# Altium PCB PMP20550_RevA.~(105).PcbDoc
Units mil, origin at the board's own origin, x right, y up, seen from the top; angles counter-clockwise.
Board outline 1966.66 x 1968.77 mil, 4 copper layers (Top Layer, POWER, GNDS, Bottom Layer), stack 79.834 mil thick; 55 components, 23 nets, 128 pads, 85 vias.
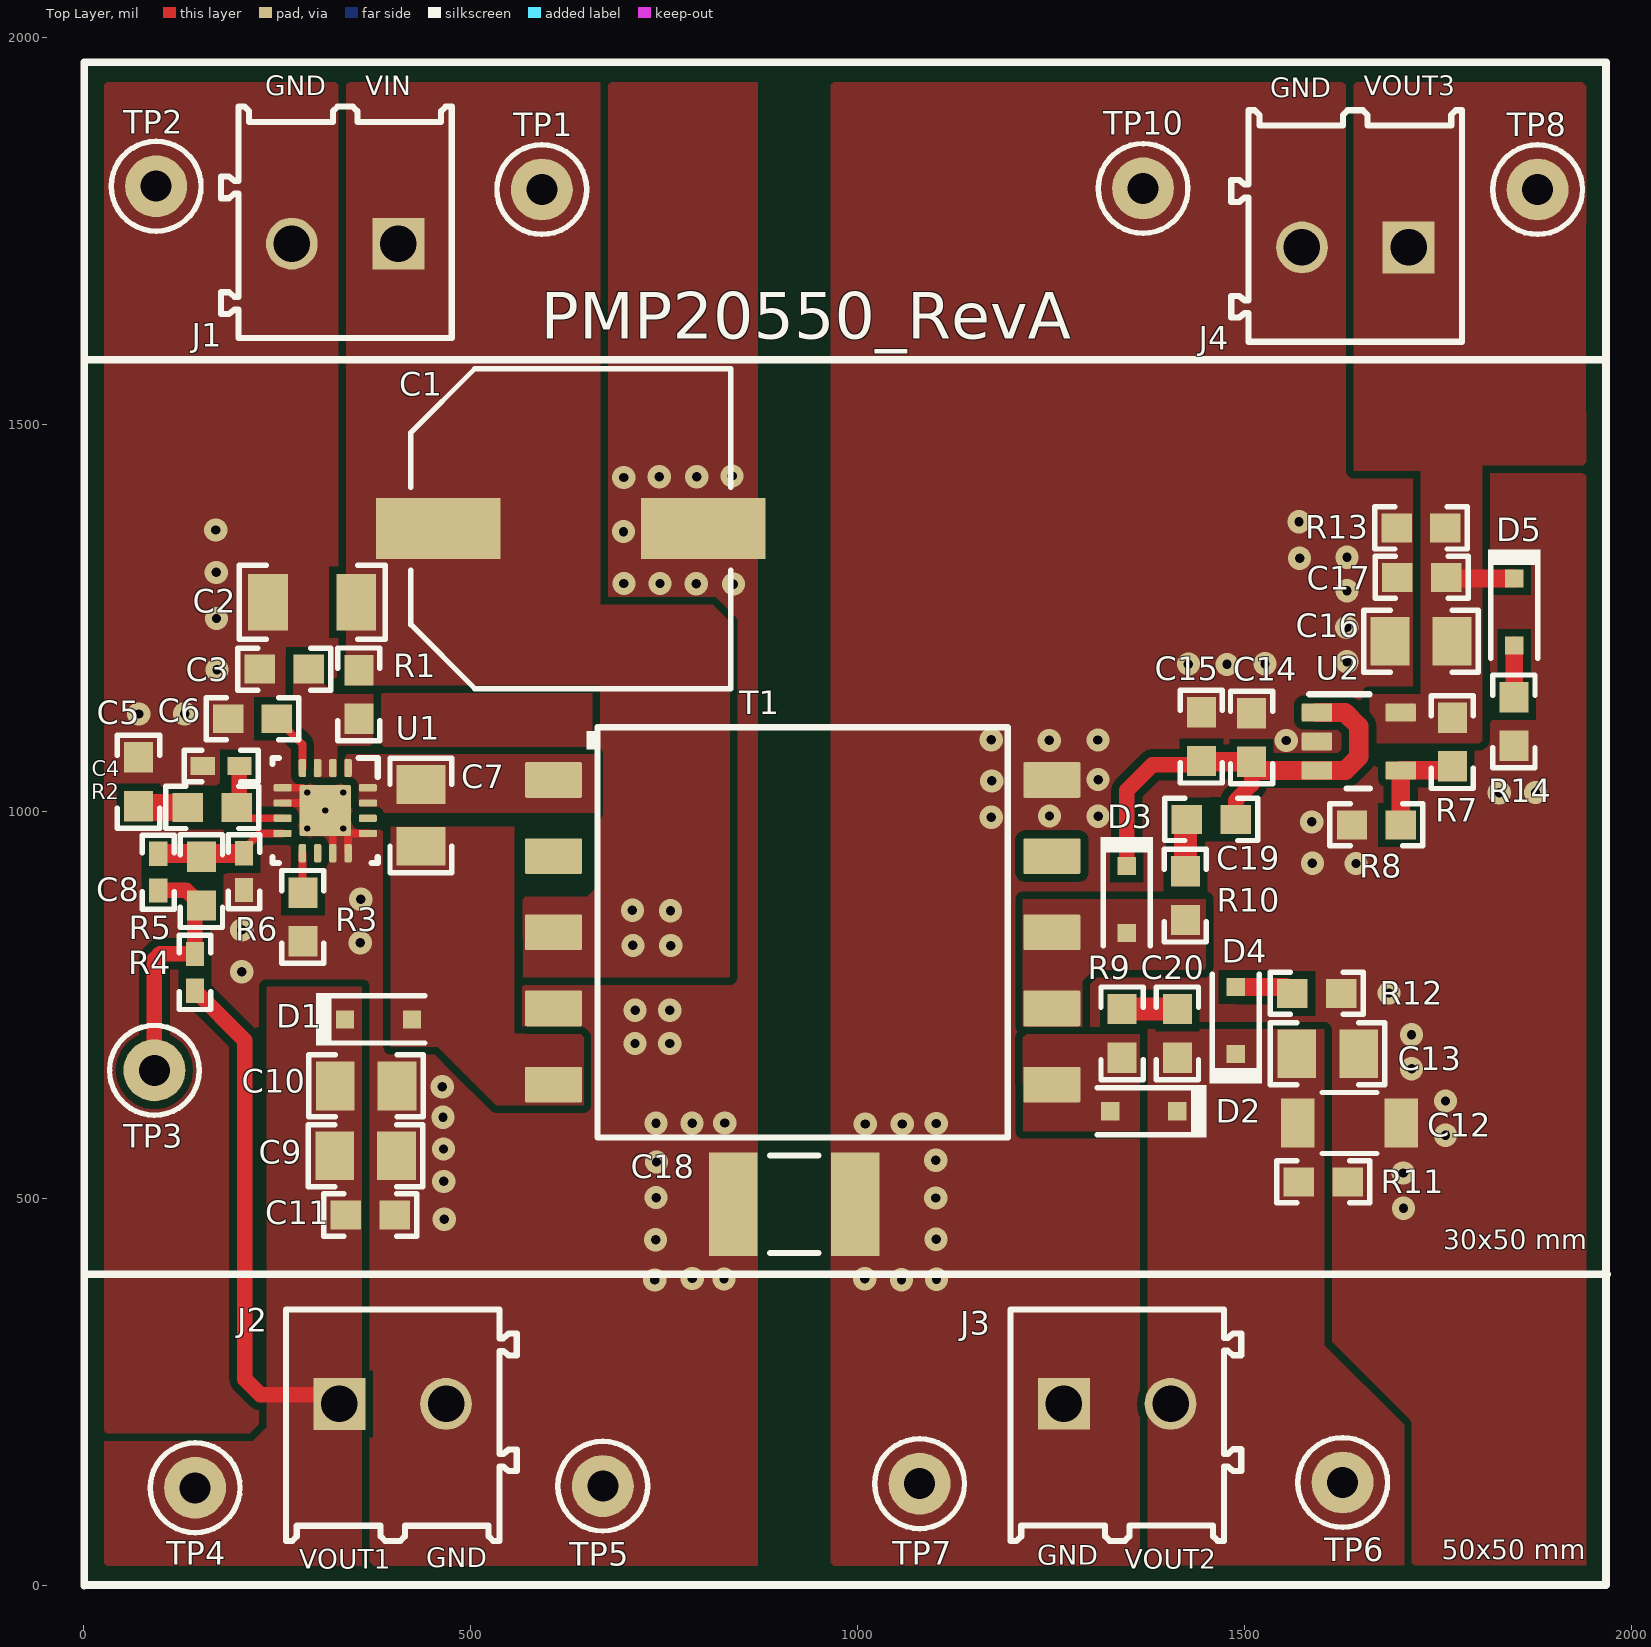
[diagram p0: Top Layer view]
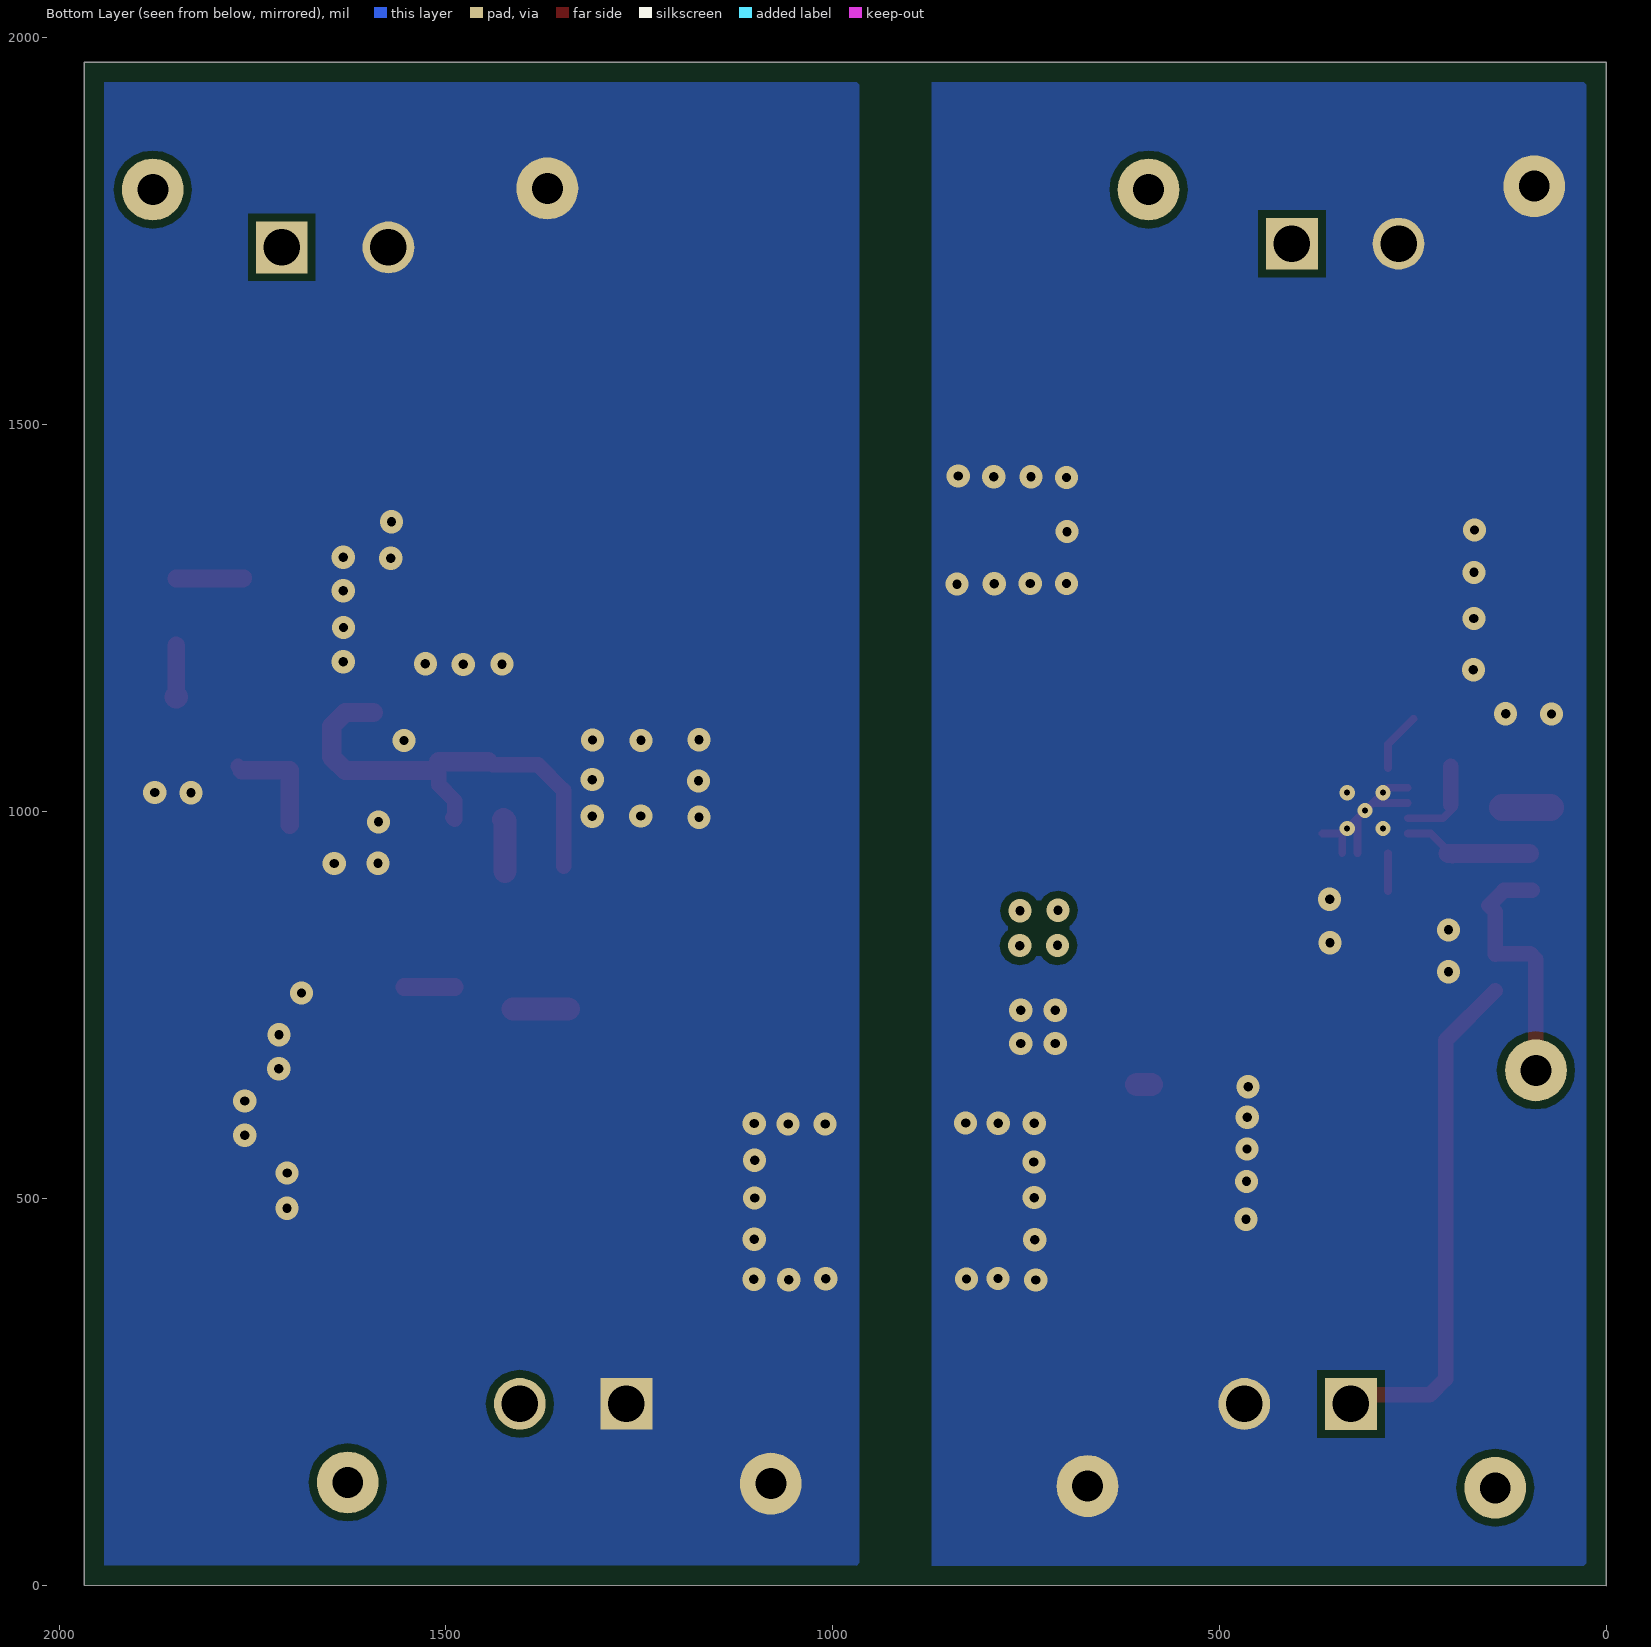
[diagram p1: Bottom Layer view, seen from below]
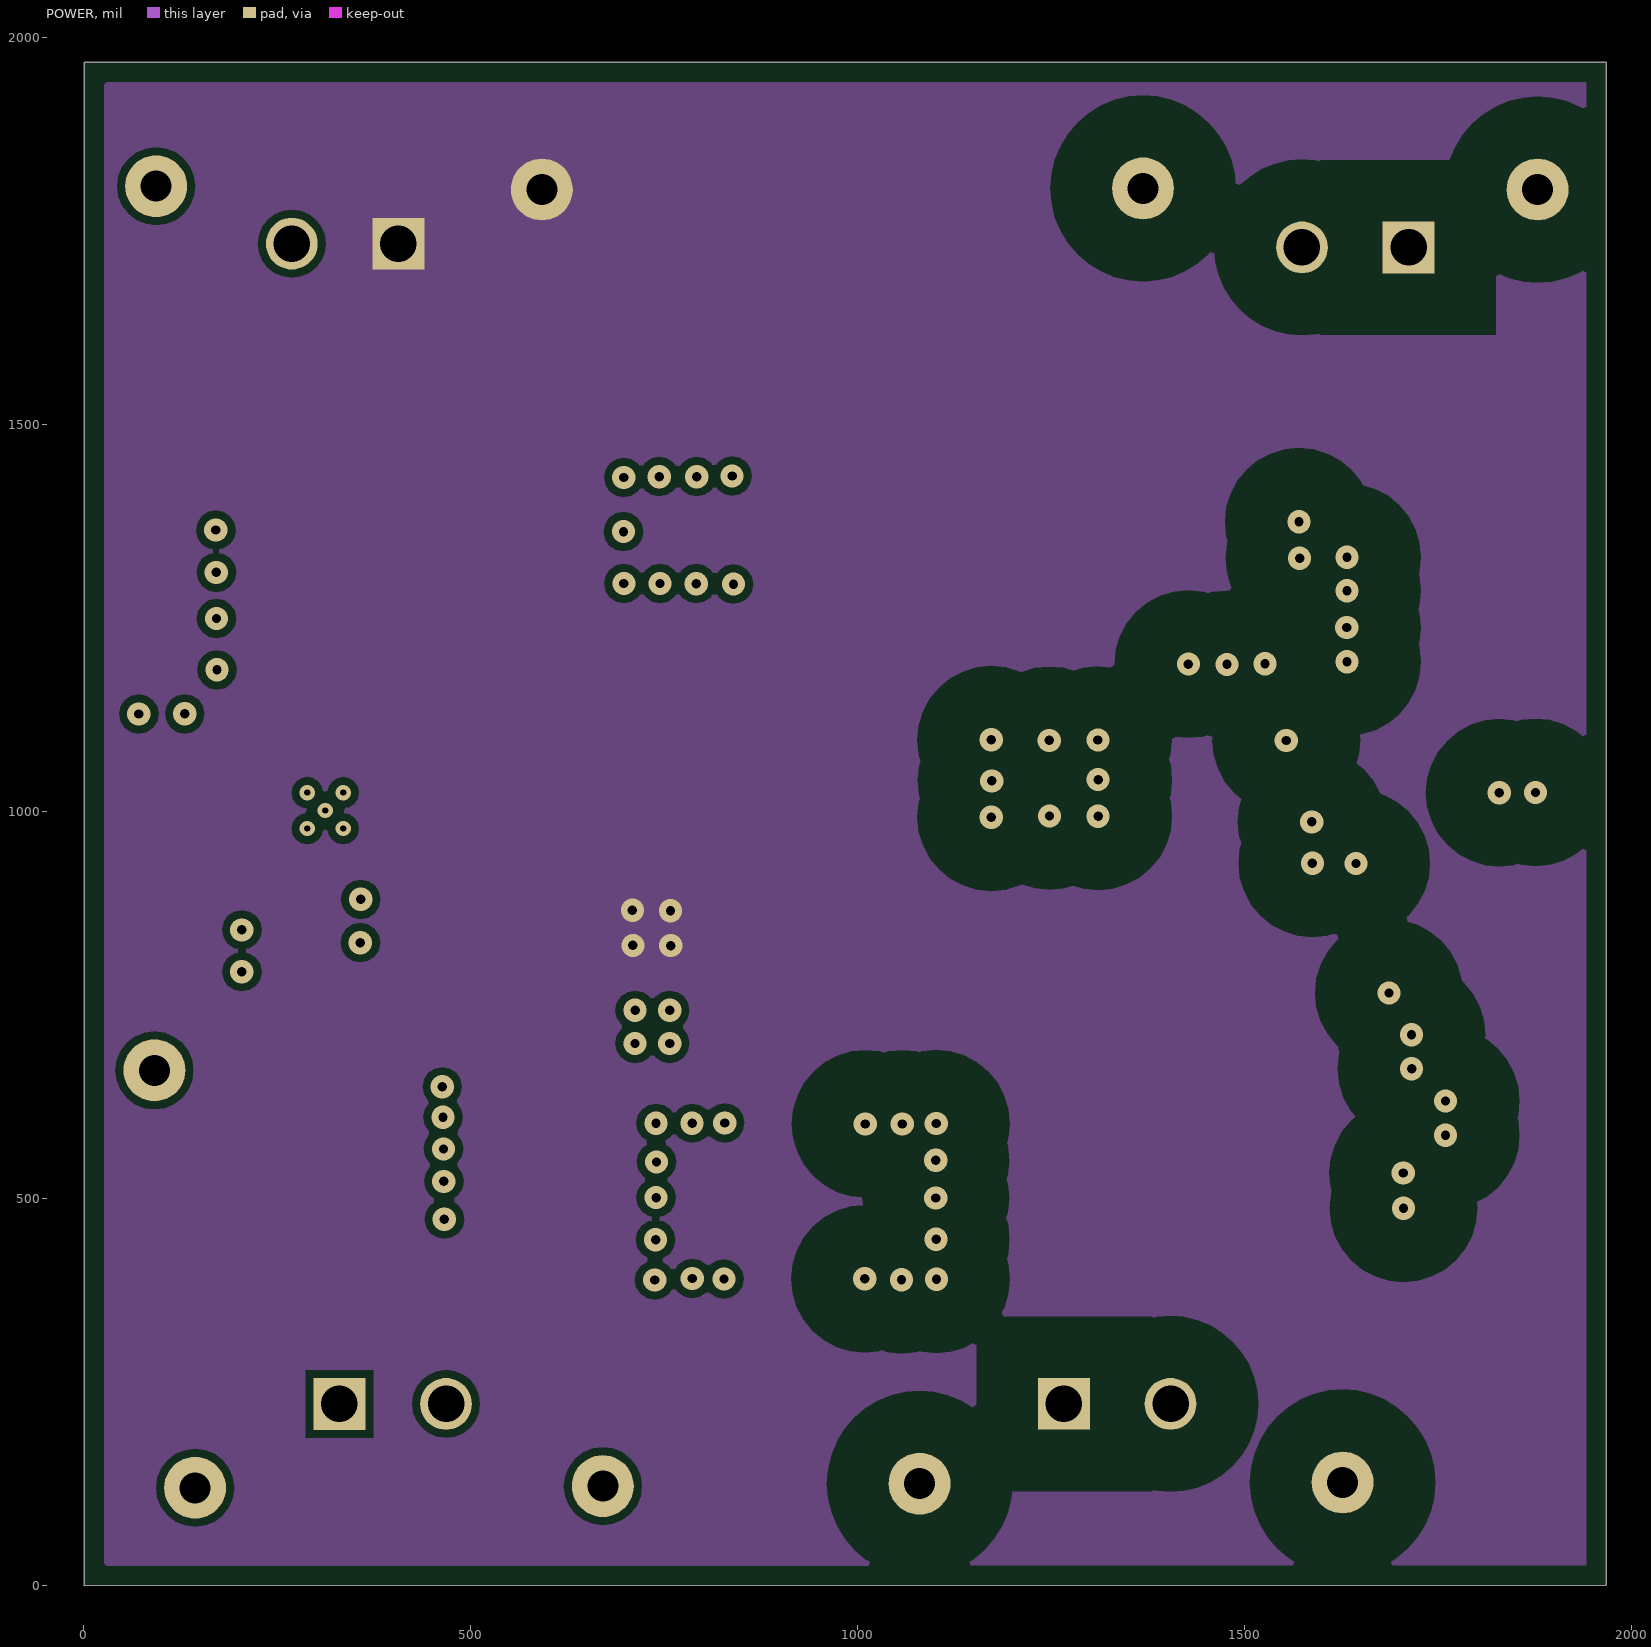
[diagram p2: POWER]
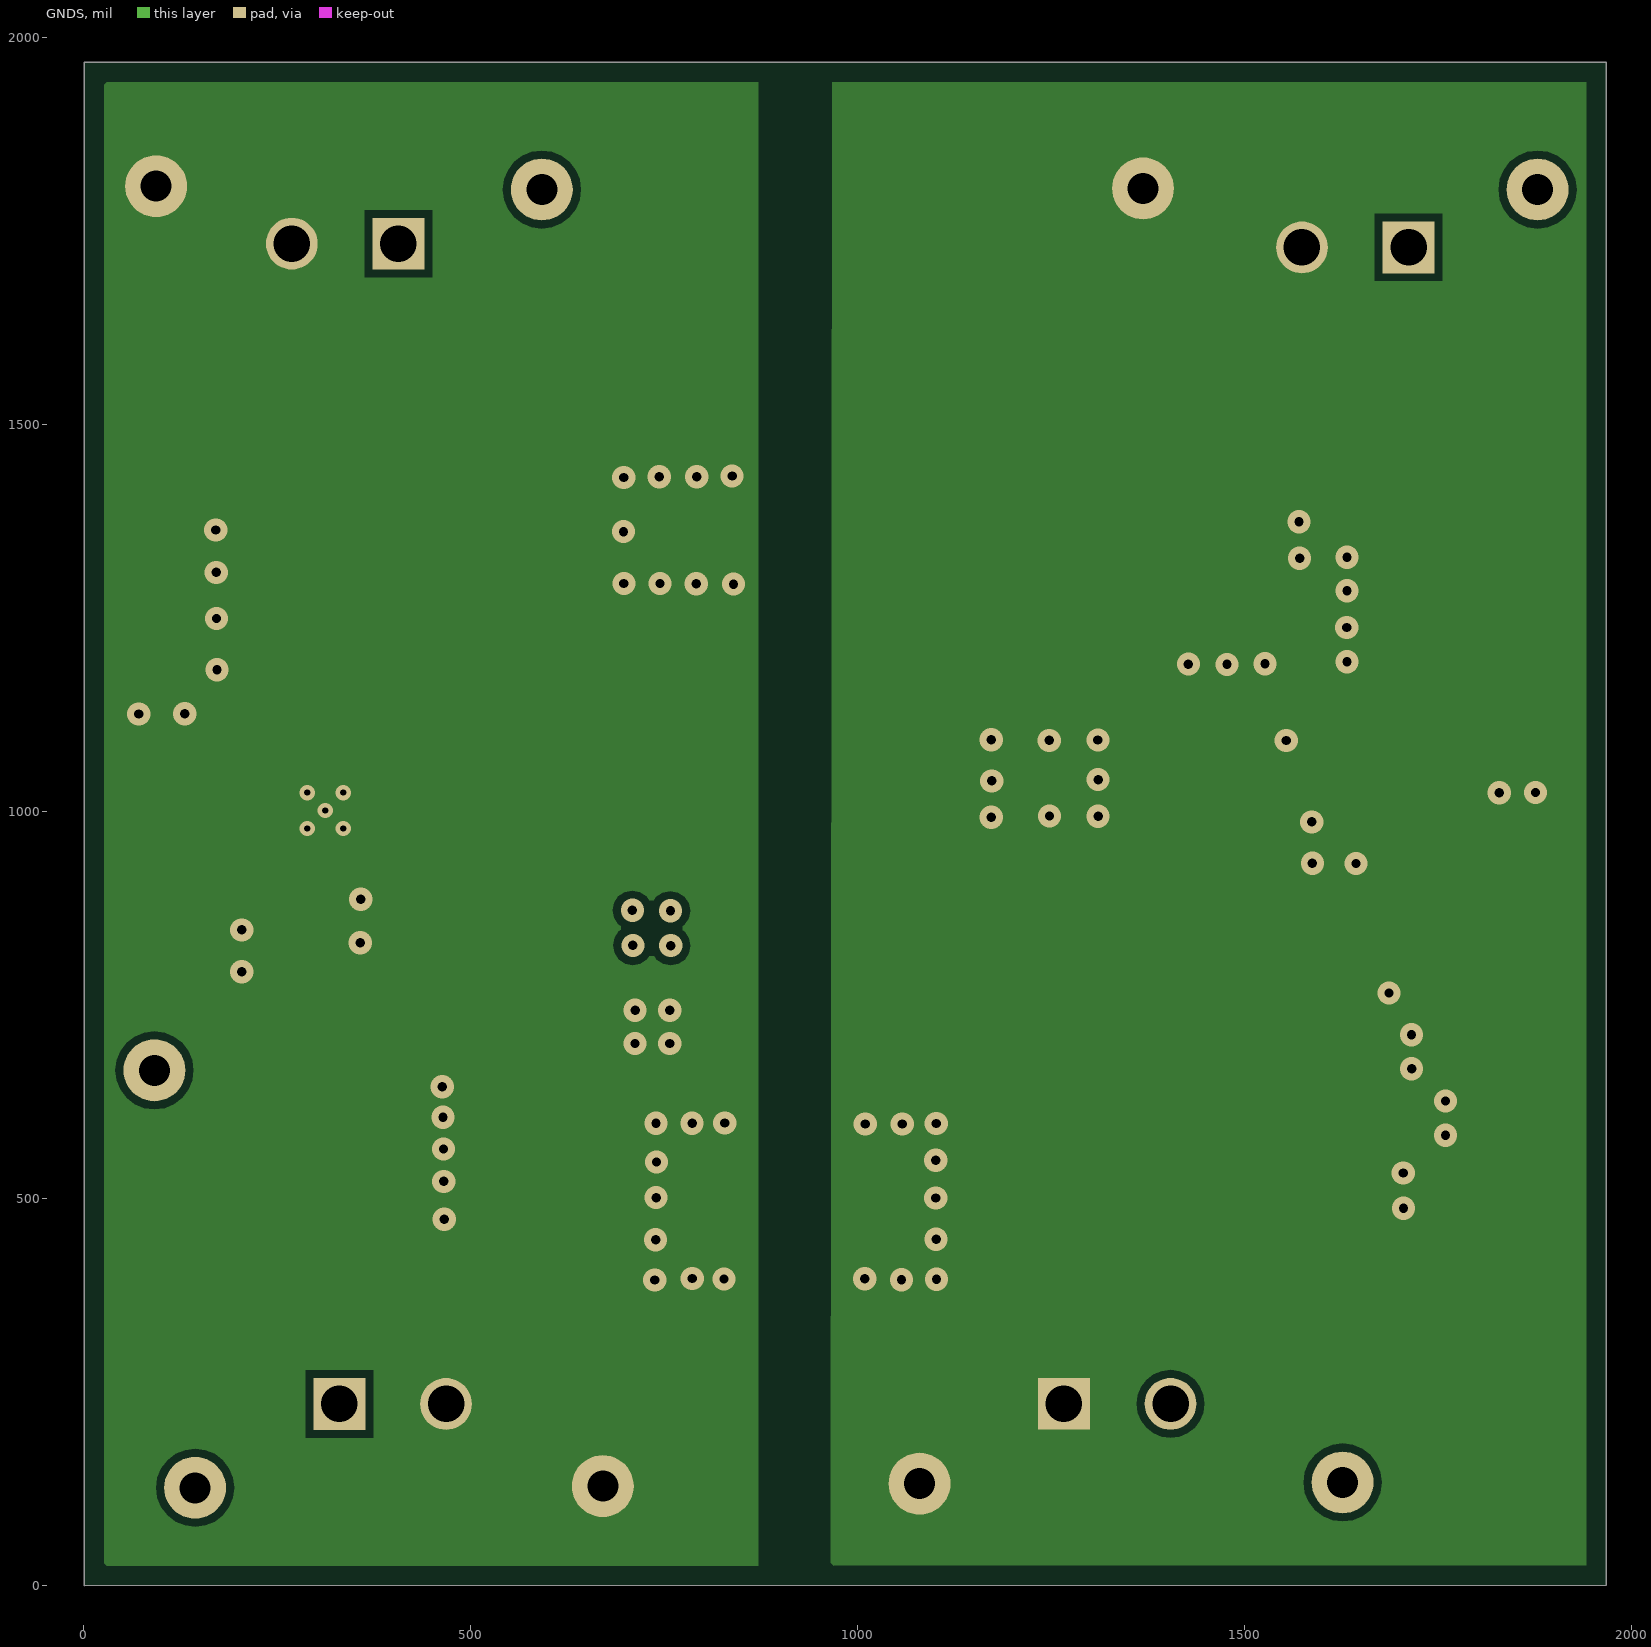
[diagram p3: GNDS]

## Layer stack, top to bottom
Top Solder: solder mask 0.4, Solder Resist, Dk 3.5
Top Layer: signal copper 1.4
Dielectric1: core 59.2, FR-4, Dk 4.8
POWER: signal copper 1.417
Dielectric 3: prepreg 5, Dk 4.2
GNDS: signal copper 1.417
Dielectric 2: core 10, Dk 4.2
Bottom Layer: signal copper 1.4
Bottom Solder: solder mask 0.4, Solder Resist, Dk 3.5

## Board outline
0.76,-0.43 0.76,1968.34 0.81,1968.29 1967.33,1968.29 1967.42,1968.2 1967.42,0.32 1967.36,0.38

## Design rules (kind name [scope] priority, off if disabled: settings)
AcuteAngle [All] p1: minimum=4.50000000000000E+0001 checktracksonly=FALSE
AssemblyTestPointUsage [All] p1: valid=2
BoardOutlineClearance BoardOutlineClearance_MountingHoles [OnCopper and InComponentClass('Mounting Holes')] p1: gap=40
BoardOutlineClearance BoardOutlineClearance_Poly [OnCopper and IsPoly] p2: gap=25
BoardOutlineClearance [OnCopper and Not InComponentClass('Logo') and not InComponentClass('FiducialMark') and not InRegion(1000,500,4000,800) and not InPoly] p3: gap=40
Clearance Clearance_2 [InNet('NetC1_1') vs InNetClass('Undefined')] p1: gap=80
Clearance Clearance_1 [InNet('GND') vs InNet('GND2')] p2: gap=80
Clearance Clearance_Keepouts [((IsTrack Or IsArc) And Not InPoly) And IsFree and IsKeepOut vs ((IsTrack Or IsArc) And Not InPoly) And IsFree and IsKeepOut] p3: gap=0
Clearance Clearance_Poly [InPolygon] p4: gap=10
Clearance [All] p5: gap=5
ComponentClearance ComponentClearance_MountingHoles_FiducialMarks [InComponentClass('Mounting Holes') vs InComponentClass('FiducialMark')] p1: gap=50 collisioncheckmode=3 verticalgap=10 showdistances=FALSE
ComponentClearance ComponentClearance_Shunt [InComponentClass('Header') vs InComponentClass('Shunt')] p2: gap=0 collisioncheckmode=3 verticalgap=0 showdistances=FALSE
ComponentClearance ComponentClearance_Logo [InComponentClass('Logo')] p3: gap=50 collisioncheckmode=3 verticalgap=10 showdistances=FALSE
ComponentClearance ComponentClearance_ScrewToNut [(HasFootprint('NY PMS 440 0025 PH')) vs (HasFootprint('Keystone_1902C'))] p4: gap=5 collisioncheckmode=3 verticalgap=10 showdistances=FALSE
ComponentClearance ComponentClearance_MountingHoles [InComponentClass('Mounting Holes')] p5: gap=250 collisioncheckmode=3 verticalgap=100000 showdistances=FALSE
ComponentClearance ComponentClearance_SmallPassives [HasFootprint('0201*') or HasFootprint('0402*') or HasFootprint('0508') or HasFootprint('0603*') or HasFootprint('0612') or HasFootprint('0805*') or HasFootprint('0815*') or HasFootprint('0830*') or HasFootprint('1206*') or HasFootprint('1210*') or HasFootprint('1808*') or HasFootprint('1812*') or HasFootprint('1825*') or HasFootprint('2010*') or HasFootprint('2220*') or HasFootprint('2225*') or HasFootprint('2512*') or HasFootprint('2728*') or HasFootprint('3518*') vs HasFootprint('0201*') or HasFootprint('0402*') or HasFootprint('0508') or HasFootprint('0603*') or HasFootprint('0612') or HasFootprint('0805*') or HasFootprint('0815*') or HasFootprint('0830*') or HasFootprint('1206*') or HasFootprint('1210*') or HasFootprint('1808*') or HasFootprint('1812*') or HasFootprint('1825*') or HasFootprint('2010*') or HasFootprint('2220*') or HasFootprint('2225*') or HasFootprint('2512*') or HasFootprint('2728*') or HasFootprint('3518*')] p6: gap=14.96 collisioncheckmode=3 verticalgap=10 showdistances=FALSE
ComponentClearance ComponentClearance_THtoSMT [IsThruComponent vs IsSMTComponent] p7: gap=40 collisioncheckmode=3 verticalgap=30 showdistances=FALSE
ComponentClearance ComponentClearance_THtoTH [IsThruComponent vs IsThruComponent] p8: gap=30 collisioncheckmode=3 verticalgap=30 showdistances=FALSE
ComponentClearance [All] p9: gap=30 collisioncheckmode=3 verticalgap=10 showdistances=FALSE
DiffPairsRouting [All] p1: maxlimit=100 minlimit=10 mostfreqgap=10 toplayer_minwidth=15 toplayer_maxwidth=15 toplayer_prefwidth=15 midlayer1_minwidth=15 midlayer1_maxwidth=15 midlayer1_prefwidth=15 midlayer2_minwidth=15 midlayer2_maxwidth=15 midlayer2_prefwidth=15 bottomlayer_minwidth=15 bottomlayer_maxwidth=15 bottomlayer_prefwidth=15 maxuncoupledlength=1000
FabricationTestPointUsage TestPointUsage [All] p1: valid=2 allowmultiple=FALSE
FabricationTestpoint Testpoint [All] p1: side=3 testpointundercomponent=TRUE minsize=40 maxsize=100 preferedsize=60 minholesize=0 maxholesize=40 preferedholesize=32 testpointgrid=1 allowsidetop=TRUE allowsidebottom=TRUE usegrid=TRUE gridtolerance=0.01
FanoutControl Fanout_LCC [IsLCC] p1: bgadir=Out bgaviamode=Centered fanoutstyle=Auto fanoutdirection=Alternating viagrid=1 // Fanout_LCC (Default Rule)
FanoutControl Fanout_BGA [IsBGA] p2: bgadir=Out bgaviamode=Centered fanoutstyle=Auto fanoutdirection=Alternating viagrid=1 // Fanout_BGA (Default Rule)
FanoutControl Fanout_Default [All] p4: bgadir=Out bgaviamode=Centered fanoutstyle=Auto fanoutdirection=Alternating viagrid=1 // Fanout_Default (Default Rule)
FanoutControl Fanout_Small [(CompPinCount < 5)] p5: bgadir=Out bgaviamode=Centered fanoutstyle=Auto fanoutdirection=OutThenIn viagrid=1 // Fanout_Small (Default Rule)
HoleSize [All] p1: absolutevalues=TRUE maxlimit=251 minlimit=7.87 maxpercent=80.000 minpercent=20.000
MinimumAnnularRing MinimumAnnularRing_ThermalPadVias [IsVia and InAnyComponent] p1: minimumring=5.91
MinimumAnnularRing [All] p2: minimumring=8
MinimumSolderMaskSliver MinimumSolderMaskSliver_Logo [InComponentClass('Logo') vs InComponentClass('Logo')] p1: minsoldermaskwidth=0.7
MinimumSolderMaskSliver [All] p2: minsoldermaskwidth=3.94
PlaneConnect [All] p1: planeconnectstyle=Direct reliefexpansion=10 reliefentries=4 reliefconductorwidth=10 reliefairgap=10
PolygonConnect [All] p1: connectstyle=Direct reliefconductorwidth=10 reliefentries=4 polygonreliefangle="90 Angle" airgapwidth=10
RoutingVias ThermalPadVias [IsVia and InAnyComponent] p1: holewidth=7.87 width=19.68 viastyle="Through Hole" minholewidth=7.87 minwidth=19.68 maxholewidth=12.99 maxwidth=23.62
RoutingVias [All] p2: holewidth=16 width=34 viastyle="Through Hole" minholewidth=7.87 minwidth=26 maxholewidth=40 maxwidth=65
SilkToBoardRegionClearance [Not ((IsComment or IsDesignator) And (Hide <> 'False')) and not InRegion(1000,500,4000,800)] p1:
SilkToSilkClearance SilkToSilkClearance_Pb-FreeLogo [(HasFootprint('Pb-Free_Overlay_Medium') OR HasFootprint('Pb-Free_Overlay_Small')) vs (HasFootprint('Pb-Free_Overlay_Medium') OR HasFootprint('Pb-Free_Overlay_Small'))] p1: silktosilkclearance=0
SilkToSilkClearance [All] p2: silktosilkclearance=0
SilkToSolderMaskClearance SilkToComponentPadClearance [IsPad and InAnycomponent] p1: minsilkscreentomaskgap=4 clearancetoexposedcopper=TRUE
SilkToSolderMaskClearance "Silk to Solder Mask Opening" [All] p2: minsilkscreentomaskgap=0 clearancetoexposedcopper=FALSE
SolderMaskExpansion [All] p1: expansion=1.97
Width [All] p1: maxlimit=100 minlimit=6 preferedwidth=10 checkconnectedcopper=TRUE
15 further rules are at their usual default settings.

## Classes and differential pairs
net class Undefined: GND2 NetC12_1 NetC14_1 NetC16_1 NetC19_2 NetC20_2 NetD2_2 NetD3_2 NetD4_2 NetD5_2 NetR7_1

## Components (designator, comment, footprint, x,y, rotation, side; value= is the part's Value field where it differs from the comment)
C1 "EEE-FC1V221P" SM_RADIAL_G 629.36,1365.64 r0 top
C2 "GMK316AB7106KL" 1206 295.27,1270.61 r180 top
C3 "C1608X7R1E104K080AA" 0603 259.1,1184.09 r180 top
C4 "GRM155R71E333KA88D" 0402 177.65,1058.89 r180 top
C5 "C1608X7R1E104K080AA" 0603 70.82,1038.63 r90 top
C6 "C1608X7R1E104K080AA" 0603 218.14,1119.95 r180 top
C7 "LMK212B7105KG-T" 0805_HV 435.84,995.13 r90 top
C8 "GRM1555C1H201JA01D" 0402 96.31,921.67 r90 top
C9 "GRM21BZ71A226ME15L" 0805_HV 364.22,555.04 r0 top
C10 "GRM21BZ71A226ME15L" 0805_HV 364.92,645.48 r0 top
C11 "C0603X104K8RACTU" 0603 370.36,478.58 r0 top
C12 "C3216X5R1E336M160AC" 1206_180 1635.8,597.58 r0 top
C13 "08053C104KAT2A" 0805_HV 1607.68,687.06 r0 top
C14 "GRM188Z71A106MA73D" 0603 1509.32,1095.78 r90 top
C15 "C1608X7R1E104K080AA" 0603 1444.34,1096.88 r90 top
C16 "C2012X7R1E474K125AA" 0805_HV 1728.32,1220.29 r180 top
C17 "C0603X104K8RACTU" 0603 1729.2,1302.77 r180 top
C18 "GR443QR73D102KW01L" 1812 918.24,492.28 r180 top
C19 "GRM1885C1H111JA01D" 0603 1457.26,989.87 r180 top
C20 "GRM1885C1H111JA01D" 0603 1413.46,713.37 r90 top
D1 "PMEG2020EJ,115" SOD-323F 380.91,731.37 r0 top
D2 "PMEG2020EJ,115" SOD-323F 1369.91,612.6 r180 top
D3 "PMEG2020EJ,115" SOD-323F 1348.01,886.28 r270 top
D4 "MMSZ5235BS-7-F" SOD-323 1488.8,729.89 r90 top
D5 "MMSZ5235BS-7-F" SOD-323 1848.7,1257.89 r270 top
J1 "1984617" Phoenix_1984617 337.81,1733.95 r180 top
J2 "1984617" Phoenix_1984617 399.35,234.48 r0 top
J3 "1984617" Phoenix_1984617 1335.67,234.61 r0 top
J4 "1984617" Phoenix_1984617 1643.31,1729.21 r180 top
R1 "ERJ-3GEY0R00V" 0603 355.63,1151.46 r90 top
R2 "RC0603FR-073K01L" 0603 165.98,1005.32 r0 top
R3 "CRCW0603162KFKEA" 0603 283.22,863.89 r90 top
R4 "ERJ-2RKF49R9X" 0402 143.75,792.24 r270 top
R5 "CRCW060330K9FKEA" 0603 152.08,910.13 r270 top
R6 "ERJ-2RKF1002X" 0402 207.01,922.32 r90 top
R7 "RC0603FR-0778K7L" 0603 1768.81,1089.81 r90 top
R8 "CRCW060324K9FKEA" 0603 1670.58,982.84 r0 top
R9 "CPF0603B1K62E" 0603 1341.88,713.37 r270 top
R10 "CPF0603B1K62E" 0603 1423.73,891.39 r270 top
R11 "CPF0603B1K62E" 0603 1601.93,521.52 r0 top
R12 "CPF0603B1K62E" 0603 1593.62,765.04 r0 top
R13 "CPF0603B1K62E" 0603 1728.32,1366.62 r180 top
R14 "CPF0603B1K62E" 0603 1848.32,1116.55 r270 top
T1 "750316553" Wurth_750316553 929.2,844.01 r0 top
TP1 "5000" Keystone5000 592.04,1803.94 r90 top
TP2 "5001" Keystone5001 93.57,1808.22 r90 top
TP3 "5003" Keystone5003 91.35,665.59 r0 top
TP4 "VBUS" Keystone5000 143.95,126.09 r90 top
TP5 "5001" Keystone5001 670.84,128.24 r90 top
TP6 "5000" Keystone5000 1627,132.97 r0 top
TP7 "5001" Keystone5001 1080.24,131.4 r0 top
TP8 "5000" Keystone5000 1878.95,1803.95 r0 top
TP10 "5001" Keystone5001 1369.04,1805.37 r90 top
U1 "TPS55340QRTERQ1" RTE0016C 312.12,1001.24 r270 top
U2 "TPS73201QDBVRQ1" DBV0005A_N 1647.84,1090.6 r0 top

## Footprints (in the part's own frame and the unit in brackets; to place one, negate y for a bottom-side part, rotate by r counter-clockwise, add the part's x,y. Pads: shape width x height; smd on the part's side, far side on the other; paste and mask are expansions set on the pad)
0402 [mm] "0402 from SM-752 data"
  rect 0.8x0.6 smd: 1(-0.6,0) 2(0.6,0)
  silkscreen extent -1.22,-0.52 1.22,0.52, body extent -0.55,-0.3 0.55,0.3, height 0.6
0603 [mm] "0603 from SM-752 data"
  rect 1x0.95 smd: 1(-0.8,0) 2(0.8,0)
  silkscreen extent -1.52,-0.69 1.52,0.69, body extent -0.87,-0.47 0.87,0.47, height 1
0805_HV [mil] "0805 with 30mil clearance between pads"
  rect 50x63 smd: 1(-40,0) 2(40,0)
  silkscreen extent -74,-40 74,40, body extent -43,-29 43,29, height 57
1206 [mm] "1206 from SM-752 data"
  rect 1.3x1.85 smd: 1(-1.45,0) 2(1.45,0)
  silkscreen extent -2.4,-1.21 2.4,1.21, body extent -1.7,-0.9 1.7,0.9, height 1.35
1206_180 [mm] "1206_180"
  rect 1.1x1.6 smd: 1(-1.7,0) 2(1.7,0)
  silkscreen extent -0.9,-1 0.9,1, body extent -1.75,-0.95 1.75,0.95, height 1.8
1812 [mm]
  rect 1.6x3.4 smd: 1(-2,0) 2(2,0)
  silkscreen extent -0.8,-1.6 0.8,1.6, body extent -2.4,-1.7 2.4,1.7, height 1.35
DBV0005A_N [mm] "SOT23, 5-Leads, Body 2.9x1.6mm, Pitch 0.95mm, Lead Span 2.8mm, IPC Medium Density"
  rrect17% 1x0.6 smd: 1(-1.375,0.95) 2(-1.375,0) 3(-1.375,-0.95) 4(1.375,-0.95) 5(1.375,0.95)
  silkscreen extent -1.63,-1.55 0.38,1.55, body extent -1.42,-1.46 1.42,1.46, height 1.09
Keystone5000 [mil] "For Keystone 500x miniature loop terminals"
  round 80 hole 40: 1(0,0)
  silkscreen extent -58,-58 58,58, body extent -49,-49 49,49, height 182
Keystone5001 [mil] "For Keystone 500x miniature loop terminals"
  round 80 hole 40: 1(0,0)
  silkscreen extent -58,-58 58,58, body extent -49,-49 49,49, height 182
Keystone5003 [mil] "For Keystone 500x miniature loop terminals"
  round 80 hole 40: 1(0,0)
  silkscreen extent -58,-58 58,58, body extent -49,-49 49,49, height 182
Phoenix_1984617 [mm] "Terminal Block, 3.5mm, 2x1, TH"
  rect 1.7x1.7 hole 1.2: 1(-1.75,0)
  round 1.7 hole 1.2: 2(1.75,0)
  silkscreen extent -3.5,-4.5 4.07,3.1, body extent -3.5,-4.5 4.07,3.1, height 9
RTE0016C [mm] "Texas Insturments"
  rrect42% 0.6x0.24 smd: 1(-1.4,0.75) 2(-1.4,0.25) 3(-1.4,-0.25) 4(-1.4,-0.75) 9(1.4,-0.75) 10(1.4,-0.25) 11(1.4,0.25) 12(1.4,0.75)
  rrect42% 0.24x0.6 smd: 5(-0.75,-1.4) 6(-0.25,-1.4) 7(0.25,-1.4) 8(0.75,-1.4) 13(0.75,1.4) 14(0.25,1.4) 15(-0.25,1.4) 16(-0.75,1.4)
  rrect6% 1.55x1.55 on Top Paste: 17(0,0)
  rrect6% 1.68x1.68 smd paste-0.85: 17(0,0)
  silkscreen extent -1.72,-1.73 1.72,1.73, body extent -1.57,-1.57 1.58,1.58, height 0.81
SM_RADIAL_G [mm] "10 x 10.2mm:  Panasonic G"
  rect 4.1x2 smd: 1(-4.35,0) 2(4.35,0)
  silkscreen extent -5.25,-5.25 5.25,5.25, body extent -5.25,-5.25 5.25,5.25, height 10.5
SOD-323 [mm] "NXP recommended land pattern"
  rect 0.6x0.6 smd paste-0.05: 1(-1.1,0) 2(1.1,0)
  silkscreen extent -2.06,-0.86 1.53,0.86, body extent -1.3,-0.67 1.3,0.68, height 1.1
SOD-323F [mm] "NXP recommended land pattern"
  rect 0.6x0.6 smd paste-0.05: 1(-1.1,0) 2(1.1,0)
  silkscreen extent -2.06,-0.86 1.53,0.86, body extent -1.35,-0.67 1.35,0.68, height 0.79
Wurth_750316553 [mm] "SMD, 10-Leads, Body 17.75x13.46mm, Pitch 2.5mm"
  rrect9% 1.88x1.17 smd: 1(-8.18,5) 2(-8.18,2.5) 3(-8.18,0) 4(-8.18,-2.5) 5(-8.18,-5) 6(8.18,-5) 7(8.18,-2.5) 8(8.18,0) 9(8.18,2.5) 10(8.18,5)
  silkscreen extent -7.1,-6.73 6.73,6.73, body extent -8.87,-6.73 8.88,6.73, height 12.7

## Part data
C1: "CAP, AL, 220 µF, 35 V, +/- 20%, 0.15 ohm, SMD"
C2: "CAP, CERM, 10 µF, 35 V, +/- 10%, X7R, 1206"
C3 C5 C6 C15: "CAP, CERM, 0.1 µF, 25 V, +/- 10%, X7R, 0603"
C4: "OPEN, 0402"
C7: "CAP, CERM, 1 µF, 10 V, +/- 10%, X7R, 0805"
C8: "CAP, CERM, 200 pF, 50 V, +/- 5%, C0G/NP0, 0402"
C9 C10: "CAP, CERM, 22 µF, 10 V, +/- 20%, X7R, 0805"
C11 C17: "CAP, CERM, 0.1 µF, 10 V, +/- 10%, X7R, 0603"
C12: "CAP, CERM, 33 µF, 25 V, +/- 20%, X5R, 1206"
C13: "CAP, CERM, 0.1 µF, 25 V, +/- 10%, X7R, 0805"
C14: "CAP, CERM, 10 µF, 10 V, +/- 20%, X7R, 0603"
C16: "CAP, CERM, 4.7 µF, 25 V, +/- 10%, X7R, 0805"
C18: "CAP, CERM, 1000 pF, 2000 V, +/- 10%, X7R, 1812"
C19 C20: "CAP, CERM, 110 pF, 50 V, +/- 5%, C0G/NP0, 0603"
D1 D2 D3: "Diode, Schottky, 20 V, 2 A, SOD-323F"
D4 D5: "Diode, Zener, 6.8 V, 200 mW, SOD-323"
J1 J2 J3 J4: "Terminal Block, 3.5mm, 2x1, TH"
R1: "RES, 0, 5%, 0.1 W, 0603"
R2: "RES, 3.01 k, 1%, 0.1 W, 0603"
R3: "RES, 162 k, 1%, 0.1 W, 0603"
R4: "RES, 49.9, 1%, 0.1 W, AEC-Q200 Grade 0, 0402"
R5: "RES, 30.9 k, 1%, 0.1 W, 0603"
R6: "RES, 10.0 k, 1%, 0.1 W, 0402"
R7: "RES, 78.7 k, 1%, 0.1 W, 0603"
R8: "RES, 24.9 k, 1%, 0.1 W, 0603"
R9 R10 R11 R12 R13 R14: "RES, 1.62 k, 0.1%, 0.063 W, 0603"
T1: "Transformer, 52 uH, SMT"
TP1 TP6 TP8: "Test Point, Miniature, Red, TH"
TP2 TP5 TP7 TP10: "Test Point, Miniature, Black, TH"
TP3: "Test Point, Miniature, Orange, TH"
TP4: library part 5000, "Test Point, TH, Miniature, Red"
U1: "Integrated 5-A 40-V Wide Input Range Boost/SEPIC/Flyback DC-DC Regulator, RTE0016C"
U2: "Single Output Fast Transient Response LDO, 250 mA, Adjustable 1.2 to 5.5 V Output, 1.7 to 5.5 V Input, 5-pin SOT-23 (DBV), -40 to 125 degC, Green (RoHS & no Sb/Br)"

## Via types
v1: diameter 30, hole 12, Top Layer to Bottom Layer, tented top, 73 vias
v2: diameter 30, hole 12, Top Layer to Bottom Layer, 7 vias
v3: diameter 19.68, hole 7.87, Top Layer to Bottom Layer, tented top, 5 vias

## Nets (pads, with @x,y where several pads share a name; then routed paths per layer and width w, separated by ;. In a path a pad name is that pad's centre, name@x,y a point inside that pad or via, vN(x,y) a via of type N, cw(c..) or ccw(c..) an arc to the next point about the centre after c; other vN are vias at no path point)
GND: C1.2 C2.2 C3.2 C4.2 C5.2 C6.2 C9.2 C10.2 C11.2 C18.2 J1.2 J2.2 R3.1 R6.1 T1.4 TP2.1 TP5.1 U1.5 U1.6 U1.11 U1.12 U1.13 U1.17@312.12,1001.24 | length 241.9
  Top Layer w10: U1.6 U1.17@302.28,1011.09 ; U1.5 U1.17@282.6,1030.77 ; v3(288.9,1024.47) U1.17@302.28,1011.09 ; U1.11 U1.17@321.97,991.4 ; U1.12 U1.17@341.65,971.72 ; U1.13 U1.17@341.65,971.72 ; U1.17@302.28,1011.09 v3(312.12,1001.24) U1.17@321.97,991.4 ; U1.17@321.97,991.4 U1.17@341.65,971.72
  other v1: 737.88,394.62 827.36,395.96 786.45,396.54 739.09,446.78 466,473.2 739.73,501.11 465.38,522.09 740.21,547.21 464.87,564.01 739.69,597.18 786.29,597.18 828.41,597.62 464.36,604.9 463.34,644.27 712.54,700.39 757.29,700.39 712.62,743.22 757.28,743.22 204.31,793 357.47,830.52 204.31,847.13 357.97,886.58 71.15,1126.18 130.55,1126.39 172.22,1183.22 171.54,1249.54 839.68,1293.98 698.06,1294.81 744.8,1294.81 791.55,1294.53 171.38,1309.15 697.5,1361.82 170.72,1363.82 697.99,1431.81 743.83,1432.79 792.14,1432.79 837.98,1433.78
  other v3: 288.9,978.02 335.35,978.02 335.35,1024.47
GND2: C12.2 C13.2 C14.2 C15.2 C16.2 C17.2 C18.1 J3.1 J4.2 R8.1 R11.2 R12.2 R13.2 R14.2 T1.10 TP7.1 TP10.1 U2.2
  other v1: 1056.94,395.02 1009.28,396.19 1102.08,395.5 1101.6,447.37 1705.62,487.37 1101.12,500.67 1705.33,532.94 1101.14,549.41 1760.02,581.64 1010.03,596.37 1057.84,596.37 1101.71,596.86 1760.02,626.08 1716.15,667.66 1715.87,711.52 1686.82,765.64 1587.91,933.34 1644.37,932.95 1587.14,986.73 1248.24,994.31 1311,993.97 1829.49,1024.37 1876.35,1024.75 1311,1041.29 1247.9,1092.04 1310.65,1092.39 1554.21,1091.83 1477.59,1190.24 1427.64,1190.58 1526.64,1190.98 1632.65,1193.61 1632.37,1237.96 1632.65,1285.38 1571.42,1327.37 1632.65,1328.61 1570.49,1374.51
  other v2: 1172.93,992.8 1173.58,1039.7 1172.93,1092.84
NetC1_1: C1.1 C2.1 J1.1 R1.2 T1.3 TP1.1
  other v2: 709.69,827.07 758.53,826.75 709.04,872.35 758.2,871.71
NetC3_1: C3.1 R1.1 U1.2 U1.3
NetC4_1: C4.1 R2.2 U1.7 | length 120.4
  Top Layer w10: R2.2@201.27,1009.12 R2.2 211.39,991.4 U1.7
  Top Layer w20: R2.2@201.27,1009.12 C4.1
NetC5_1: C5.1 R2.1 | length 64.4
  Top Layer w20: C5.1 C5.1@72.63,1005.32
  Top Layer w35: C5.1@72.63,1005.32 R2.1
NetC6_1: C6.1 U1.4 | length 77.2
  Top Layer w10: C6.1 282.6,1086.99 U1.4
NetC7_1: C7.1 D1.2 T1.5 | length 19.1
  Top Layer w30: T1.5@588.1,647.16 T1.5
NetC7_2: C7.2 T1.1 U1.1 U1.15 U1.16
NetC8_1: C8.1 R4.1 R5.2 TP3.1 | length 329
  Top Layer w20: TP3.1 91.35,809.04 98.56,816.26 143.35,816.26 R4.1 143.75,870.3 R5.2 132.67,898.05 C8.1
NetC8_2: C8.2 R5.1 R6.2 U1.8 | length 181.8
  Top Layer w10: R6.2@198.61,943.01 227.31,971.72 U1.8
  Top Layer w20: 194.08,947.54 R6.2@198.61,943.01
  Top Layer w25: C8.2@99.61,945.84 R6.2@204.68,945.84
NetC9_1: C9.1 C10.1 C11.1 D1.1 J2.1 R4.2 TP4.1 | length 664.3
  Top Layer w20: R4.2 207.9,704.47 208.07,266.55 228.31,246.31 318.62,246.31 J2.1
NetC12_1: C12.1 C13.1 C20.1 D2.1 D4.1 J3.2 R11.1 TP6.1
NetC14_1: C14.1 C15.1 C19.1 D3.1 U2.1 U2.3 | length 613.2
  Top Layer w20: D3.1 1348.01,1027.52 1381.05,1060.55 1439.51,1060.55 C15.1 C15.1@1445.44,1064.28 ; C19.1@1491.26,992.37 C19.1 1488.76,1014.3 1509.32,1034.86 C14.1 C14.1@1520.41,1053.2
  Top Layer w25: C15.1@1445.44,1064.28 C14.1 ; C14.1@1520.41,1053.2 U2.3 1630.28,1053.2 1647.84,1070.76 1647.84,1110.28 1630.13,1128 U2.1
NetC16_1: C16.1 C17.1 D5.1 J4.1 R7.2 R13.1 TP8.1 U2.5 | length 88.7
  Top Layer w20: C17.1 C17.1@1762.27,1301.2
  Top Layer w23: C17.1@1762.27,1301.2 D5.1
NetC19_2: C19.2 R10.1 | length 67.8
  Top Layer w30: R10.1 1423.73,987.83 C19.2
NetC20_2: C20.2 R9.1 | length 71.6
  Top Layer w30: R9.1 C20.2
NetD2_2: D2.2 R9.2 T1.6
NetD3_2: D3.2 R10.2 T1.7 T1.8
NetD4_2: D4.2 R12.1 | length 65.2
  Top Layer w23: D4.2 R12.1@1553.97,773.2
NetD5_2: D5.2 R14.1 | length 66.7
  Top Layer w23: R14.1@1848.7,1148.43 D5.2
  Top Layer w30: R14.1 R14.1@1848.7,1148.43
NetR3_2: R3.2 U1.9 | length 49.2
  Top Layer w10: U1.9 R3.2@282.65,896.93
NetR7_1: R7.1 R8.2 U2.4 | length 139.4
  Top Layer w20: R7.1@1763.69,1053.2 R7.1
  Top Layer w24: R8.2 1702.07,1053.1 U2.4 R7.1@1763.69,1053.2
pads on no net: T1.2 T1.9 U1.10 U1.14 U1.17@312.12,1001.24
copper on no net: | length 103920.8
  Top Layer w1: 9623.11,1578.03 9722.79,1677.72 9842.79,1797.72 9962.79,1917.72 10082.79,2037.72 10202.79,2157.72 10322.79,2277.72 10442.79,2397.72 10562.79,2517.72 10682.79,2637.72 10742.79,2697.72 ; 9623.11,1638.03 9662.79,1677.72 9782.79,1797.72 9902.79,1917.72 10022.79,2037.72 10142.79,2157.72 10262.79,2277.72 10382.79,2397.72 10502.79,2517.72 10622.79,2637.72 10742.79,2757.72 ; 9623.11,1698.03 9722.79,1797.72 9842.79,1917.72 9962.79,2037.72 10082.79,2157.72 10202.79,2277.72 10322.79,2397.72 10442.79,2517.72 10562.79,2637.72 10682.79,2757.72 10742.79,2817.72 ; 9623.11,1758.03 9662.79,1797.72 9782.79,1917.72 9902.79,2037.72 10022.79,2157.72 10142.79,2277.72 10262.79,2397.72 10382.79,2517.72 10502.79,2637.72 10622.79,2757.72 10742.79,2877.72 ; 9623.11,1818.03 9722.79,1917.72 9842.79,2037.72 9962.79,2157.72 10082.79,2277.72 10202.79,2397.72 10322.79,2517.72 10442.79,2637.72 10562.79,2757.72 10682.79,2877.72 ; 9623.11,1878.03 9662.79,1917.72 9782.79,2037.72 9902.79,2157.72 10022.79,2277.72 10142.79,2397.72 10262.79,2517.72 10382.79,2637.72 10502.79,2757.72 10622.79,2877.72 ; 9623.11,1938.03 9722.79,2037.72 9842.79,2157.72 9962.79,2277.72 10082.79,2397.72 10202.79,2517.72 10322.79,2637.72 10442.79,2757.72 10562.79,2877.72 ; 9623.11,1998.03 9662.79,2037.72 9782.79,2157.72 9902.79,2277.72 10022.79,2397.72 10142.79,2517.72 10262.79,2637.72 10382.79,2757.72 10502.79,2877.72 ; 9623.11,2058.03 9722.79,2157.72 9842.79,2277.72 9962.79,2397.72 10082.79,2517.72 10202.79,2637.72 10322.79,2757.72 10442.79,2877.72 ; 9623.11,2118.03 9662.79,2157.72 9782.79,2277.72 9902.79,2397.72 10022.79,2517.72 10142.79,2637.72 10262.79,2757.72 10382.79,2877.72 ; 9623.11,2178.03 9722.79,2277.72 9842.79,2397.72 9962.79,2517.72 10082.79,2637.72 10202.79,2757.72 10322.79,2877.72 ; 9623.11,2238.03 9662.79,2277.72 9782.79,2397.72 9902.79,2517.72 10022.79,2637.72 10142.79,2757.72 10262.79,2877.72 ; 9623.11,2298.03 9722.79,2397.72 9842.79,2517.72 9962.79,2637.72 10082.79,2757.72 10202.79,2877.72 ; 9623.11,2358.03 9662.79,2397.72 9782.79,2517.72 9902.79,2637.72 10022.79,2757.72 10142.79,2877.72 ; 9623.11,2418.03 9722.79,2517.72 9842.79,2637.72 9962.79,2757.72 10082.79,2877.72 ; 9623.11,2478.03 9662.79,2517.72 9782.79,2637.72 9902.79,2757.72 10022.79,2877.72 ; 9623.11,2538.03 9722.79,2637.72 9842.79,2757.72 9962.79,2877.72 ; 9623.11,2598.03 9662.79,2637.72 9782.79,2757.72 9902.79,2877.72 ; 9623.11,2658.03 9722.79,2757.72 9842.79,2877.72 ; 9623.11,2718.03 9662.79,2757.72 9782.79,2877.72 ; 9623.11,2778.03 9722.79,2877.72 ; 9623.11,2838.03 9662.79,2877.72 ; 9662.79,1557.72 9782.79,1677.72 9902.79,1797.72 10022.79,1917.72 10142.79,2037.72 10262.79,2157.72 10382.79,2277.72 10502.79,2397.72 10622.79,2517.72 10742.79,2637.72 ; 9722.79,1557.72 9842.79,1677.72 9962.79,1797.72 10082.79,1917.72 10202.79,2037.72 10322.79,2157.72 10442.79,2277.72 10562.79,2397.72 10682.79,2517.72 10742.79,2577.72 ; 9782.79,1557.72 9902.79,1677.72 10022.79,1797.72 10142.79,1917.72 10262.79,2037.72 10382.79,2157.72 10502.79,2277.72 10622.79,2397.72 10742.79,2517.72 ; 9842.79,1557.72 9962.79,1677.72 10082.79,1797.72 10202.79,1917.72 10322.79,2037.72 10442.79,2157.72 10562.79,2277.72 10682.79,2397.72 10742.79,2457.72 ; 9902.79,1557.72 10022.79,1677.72 10142.79,1797.72 10262.79,1917.72 10382.79,2037.72 10502.79,2157.72 10622.79,2277.72 10742.79,2397.72 ; 9962.79,1557.72 10082.79,1677.72 10202.79,1797.72 10322.79,1917.72 10442.79,2037.72 10562.79,2157.72 10682.79,2277.72 10742.79,2337.72 ; 10022.79,1557.72 10142.79,1677.72 10262.79,1797.72 10382.79,1917.72 10502.79,2037.72 10622.79,2157.72 10742.79,2277.72 ; 10082.79,1557.72 10202.79,1677.72 10322.79,1797.72 10442.79,1917.72 10562.79,2037.72 10682.79,2157.72 10742.79,2217.72 ; 10142.79,1557.72 10262.79,1677.72 10382.79,1797.72 10502.79,1917.72 10622.79,2037.72 10742.79,2157.72 ; 10202.79,1557.72 10322.79,1677.72 10442.79,1797.72 10562.79,1917.72 10682.79,2037.72 10742.79,2097.72 ; 10262.79,1557.72 10382.79,1677.72 10502.79,1797.72 10622.79,1917.72 10742.79,2037.72 ; 10322.79,1557.72 10442.79,1677.72 10562.79,1797.72 10682.79,1917.72 10742.79,1977.72 ; 10382.79,1557.72 10502.79,1677.72 10622.79,1797.72 10742.79,1917.72 ; 10442.79,1557.72 10562.79,1677.72 10682.79,1797.72 10742.79,1857.72 ; 10502.79,1557.72 10622.79,1677.72 10742.79,1797.72 ; 10562.79,1557.72 10682.79,1677.72 10742.79,1737.72 ; 10622.79,1557.72 10742.79,1677.72 ; 10682.79,1557.72 10742.79,1617.72
  Top Layer w15: 6203.99,1677.72 6613.9,1677.72 7543.64,1677.72 8403.41,1677.72 9053.25,1677.72 9623.11,1677.72 10742.79,1677.72 ; 6203.99,1797.72 6613.9,1797.72 7543.64,1797.72 8403.41,1797.72 9053.25,1797.72 9623.11,1797.72 10742.79,1797.72 ; 6203.99,1917.72 6613.9,1917.72 7543.64,1917.72 8403.41,1917.72 9053.25,1917.72 9623.11,1917.72 10742.79,1917.72 ; 6203.99,2037.72 6613.9,2037.72 7543.64,2037.72 8403.41,2037.72 9053.25,2037.72 9623.11,2037.72 10742.79,2037.72 ; 6203.99,2157.72 6613.9,2157.72 7543.64,2157.72 8403.41,2157.72 9053.25,2157.72 9623.11,2157.72 10742.79,2157.72 ; 6203.99,2277.72 6613.9,2277.72 7543.64,2277.72 8403.41,2277.72 9053.25,2277.72 9623.11,2277.72 10742.79,2277.72 ; 6203.99,2397.72 6613.9,2397.72 7543.64,2397.72 8403.41,2397.72 9053.25,2397.72 9623.11,2397.72 10742.79,2397.72 ; 6203.99,2517.72 6613.9,2517.72 7543.64,2517.72 8403.41,2517.72 9053.25,2517.72 9623.11,2517.72 10742.79,2517.72 ; 6203.99,2637.72 6613.9,2637.72 7543.64,2637.72 8403.41,2637.72 9053.25,2637.72 9623.11,2637.72 10742.79,2637.72 ; 6203.99,2757.72 6613.9,2757.72 7543.64,2757.72 8403.41,2757.72 9053.25,2757.72 9623.11,2757.72 10742.79,2757.72 ; 6203.99,2877.72 10742.79,2877.72 ; 6613.9,2997.72 6613.9,1557.72 ; 7543.64,2997.72 7543.64,1557.72 ; 8403.41,2997.72 8403.41,1557.72 ; 9053.25,2997.72 9053.25,1557.72 ; 9623.11,2997.72 9623.11,1557.72 ; 6613.9,1557.72 7543.64,1557.72 ; 6613.9,1557.72 6203.99,1557.72 6203.99,2997.72 10742.79,2997.72 10742.79,1557.72 9623.11,1557.72 ; 7543.64,1557.72 8403.41,1557.72 ; 8403.41,1557.72 9053.25,1557.72 ; 9053.25,1557.72 9623.11,1557.72

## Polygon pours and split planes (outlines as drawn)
NetC3_1 on Top Layer "Top Layer-No Net 4" (solid, pour order 34): 271.3,1202.21 270.6,1201.51 270.6,1097.93 296.64,1072.92 296.64,1043.16 315.48,1043.16 327.61,1043.16 327.61,1055.56 327.61,1085.23 374.08,1085.23 373.65,1101.6 374.31,1102.26 374.31,1151.46 324.21,1151.46 320.13,1155.55 309.59,1166.08 309.59,1202.55
NetC9_1 on Top Layer "Top Layer-No Net" (solid, pour order 44): 26.25,-2.6 26.25,186.05 218.59,186.05 237.25,204.71 236.31,205.65 236.31,773.3 359.56,773.3 359.56,25.31 421.08,-36.21
NetC7_2 on Top Layer "Top Layer-No Net 3" (solid, pour order 46): 330.27,1074.83 331.22,1073.88 661.33,1073.88 661.33,1042.72 661.33,998.74 335.74,998.74
NetC1_1 on Top Layer "Top Layer-No Net 5" (solid, pour order 48): 339.31,1944.8 339.31,1162.89 338.71,1162.29 339.37,1162.95 667.71,1162.95 667.71,1943.13 669.04,1944.45
NetC1_1 on Top Layer "Top Layer-No Net 6" (solid, pour order 52): 567.92,786.77 568.77,785.92 835.04,785.92 835.04,1245.17 815.11,1265.1 812.79,1267.42 667.45,1267.42 667.45,906.72 652.14,891.4 650.44,889.7 567.07,889.7
NetC16_1 on Top Layer "Top Layer-No Net 1" (solid, pour order 54): 1941.93,1942.72 1941.55,1943.09 1641.27,1943.09 1641.27,1527.79 1641.27,1440.4 1728.66,1440.4 1727.89,1439.63 1727.89,1151.93 1661.93,1151.93 1661.93,1088.51 1803.68,1088.51 1806,1086.19 1807.55,1087.74 1807.55,1446.59 1807.55,1447.36 1941.93,1447.36 1941.34,1581.15
NetC12_1 on Top Layer "Top Layer-No Net 8" (solid, pour order 58): 1375.13,718.42 1602.53,718.42 1603.46,717.48 1603.46,316.97 1603.46,310.42 1706.4,207.48 1706.4,10.97 1385.43,10.97 1375.13,21.26
NetD3_2 on Top Layer "Top Layer-No Net 2" (solid, pour order 60): 1213.82,886.63 1450.31,886.63 1450.31,794.24 1449.73,793.66 1447.98,795.41 1310.86,795.41 1305.05,795.41 1291.1,781.46 1290.52,780.88 1290.52,722.19 1214.41,722.19 1213.82,721.61
NetD2_2 on Top Layer "Top Layer-No Net 9" (solid, pour order 64): 1213.55,712.03 1367.63,712.03 1367.63,586.74 1367.19,587.18 1213.96,587.18
NetC7_1 on Top Layer "Top Layer-No Net 7" (solid, pour order 16): 645.92,620.59 533,620.59 481.19,672.4 457.79,695.8 396.89,695.8 396.89,730.61 396.89,761.24 396.89,777.73 396.89,782.22 396.89,980.2 556.24,980.2 556.24,712.58 645.92,712.58
GND on Top Layer "Top Layer-No Net 10" (solid, pour order 66): 871.08,7.23 871.08,1963.51 5.59,1963.51 0.81,1968.29 0.76,1968.23 0.76,-0.43
GND2 on Top Layer "Top Layer-No Net 11" (solid, pour order 68): 965.74,4.81 965.74,1958.65 975.37,1968.29 1967.33,1968.29 1967.33,0.4 1967.42,0.32
NetC1_1 on POWER "POWER-No Net" (solid, pour order 18): 0.81,1968.29 0.9,1968.2 1967.42,1968.2 1967.42,0.32 1967.36,0.38 1.56,0.38
GND2 on GNDS "GND2" (solid, pour order 28): 965.46,0.2 1967.36,0.38 1967.36,1968.26 1963.66,1964.61 967.67,1964.61
GND on GNDS "GND1" (solid, pour order 20): 871.68,6.54 7.73,6.54 1.56,0.38 0.81,1.12 0.81,1968.29 871.68,1968.29
GND2 on Bottom Layer "bot - gnd2" (solid, pour order 42): 1969.72,1967.03 1965.01,1971.74 965.71,1971.74 965.71,7.87 1972.08,7.87
GND on Bottom Layer "bot - gnd1" (solid, pour order 36): 3.49,1967.03 872.33,1967.03 872.33,1914.05 872.33,5.51 8.21,5.51 1.13,-1.56

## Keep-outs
Keep-Out Layer:
  text ".Layer_Name" at 577,-858.49 h60

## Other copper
Top Layer:
  text "Layer" at 6263.99,2907.72 h60
  text "Name" at 6673.9,2907.72 h60
  text "Material" at 7603.64,2907.72 h60
  text "Thickness" at 8463.41,2907.72 h60
  text "Constant" at 9113.25,2907.72 h60
  text "Board Layer Stack" at 9683.11,2907.72 h60
  text "1" at 6263.99,2787.72 h60
  text "Top Overlay" at 6673.9,2787.72 h60
  text "2" at 6263.99,2667.72 h60
  text "Top Solder" at 6673.9,2667.72 h60
  text "Solder Resist" at 7603.64,2667.72 h60
  text "0.40mil" at 8463.41,2667.72 h60
  text "3.5" at 9113.25,2667.72 h60
  text "3" at 6263.99,2547.72 h60
  text "Top Layer" at 6673.9,2547.72 h60
  text "Copper" at 7603.64,2547.72 h60
  text "1.40mil" at 8463.41,2547.72 h60
  text "4" at 6263.99,2427.72 h60
  text "Dielectric1" at 6673.9,2427.72 h60
  text "FR-4" at 7603.64,2427.72 h60
  text "59.20mil" at 8463.41,2427.72 h60
  text "4.8" at 9113.25,2427.72 h60
  text "5" at 6263.99,2307.72 h60
  text "POWER" at 6673.9,2307.72 h60
  text "Copper" at 7603.64,2307.72 h60
  text "1.42mil" at 8463.41,2307.72 h60
  text "6" at 6263.99,2187.72 h60
  text "Dielectric 3" at 6673.9,2187.72 h60
  text "5.00mil" at 8463.41,2187.72 h60
  text "4.2" at 9113.25,2187.72 h60
  text "7" at 6263.99,2067.72 h60
  text "GNDS" at 6673.9,2067.72 h60
  text "Copper" at 7603.64,2067.72 h60
  text "1.42mil" at 8463.41,2067.72 h60
  text "8" at 6263.99,1947.72 h60
  text "Dielectric 2" at 6673.9,1947.72 h60
  text "10.00mil" at 8463.41,1947.72 h60
  text "4.2" at 9113.25,1947.72 h60
  text "9" at 6263.99,1827.72 h60
  text "Bottom Layer" at 6673.9,1827.72 h60
  text "Copper" at 7603.64,1827.72 h60
  text "1.40mil" at 8463.41,1827.72 h60
  text "10" at 6263.99,1707.72 h60
  text "Bottom Solder" at 6673.9,1707.72 h60
  text "Solder Resist" at 7603.64,1707.72 h60
  text "0.40mil" at 8463.41,1707.72 h60
  text "3.5" at 9113.25,1707.72 h60
  text "11" at 6263.99,1587.72 h60
  text "Bottom Overlay" at 6673.9,1587.72 h60
  text ".Layer_Name" at 577,-858.49 h60
Bottom Layer:
  text ".Layer_Name" at 577,-858.49 h60

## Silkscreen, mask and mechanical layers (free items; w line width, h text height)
Top Overlay:
  lines w10: 0.76,-0.43 0.76,1968.34 0.81,1968.29 1967.33,1968.29 1967.42,1968.2 1967.42,0.32 1967.36,0.38 1.56,0.38 ; 1.37,401.99 1968.53,401.99 ; 2.15,1583.98 1965.61,1583.98
  text "GND" at 234.8,1925.94 h25
  text "VIN" at 363.98,1926.01 h25
  text "VOUT3" at 1654.52,1926 h25
  text "GND" at 1533.71,1923.51 h25
  text "PMP20550_RevA" at 590.93,1611.16 h60
  text "30x50 mm" at 1756.82,434.07 h25
  text "50x50 mm" at 1755.09,33.73 h25
  text "GND" at 1232.3,26.61 h25
  text "GND" at 442.94,23.43 h25
  text "VOUT1" at 278.39,21.65 h25
  text "VOUT2" at 1345.21,21.76 h25
  text ".Layer_Name" at 577,-858.49 h60
Bottom Overlay:
  text ".Layer_Name" at 577,-858.49 h60
Top Paste:
  text ".Layer_Name" at 577,-858.49 h60
Bottom Paste:
  text ".Layer_Name" at 577,-858.49 h60
Top Solder:
  text ".Layer_Name" at 577,-858.49 h60
  text ".Layer_Name" at 577,-858.49 h60
Bottom Solder:
  text ".Layer_Name" at 577,-858.49 h60
Drill Guide:
  text ".Layer_Name" at 577,-858.49 h60
M1 Board Outline:
  text ".Layer_Name" at 577,-858.49 h60
M2 Board Dimensions:
  rectangle: 0,-275 125,-150
  rectangle: 125,-400 500,-275
  lines w7: 0,-275 1000,-275 ; 125,-400 125,-150 ; 250,-400 250,-150 ; 500,-400 500,-150 ; 750,-400 750,-150 ; 0,-400 1000,-400 1000,-150 0,-150 0,-400
  text ".Layer_Name" at 577,-858.49 h60
M3 3D STEP Top:
  text ".Layer_Name" at 577,-858.49 h60
M4 3D STEP Bottom:
  text ".Layer_Name" at 577,-858.49 h60
M5 Assembly Top:
  lines w10: -292,-930.17 6308,-930.17 ; -292,-726.83 6310,-726.83 ; -292,-523.5 -292,-1133.5 3713,-1133.5 6310,-1133.5 6310,-523.5 -291.5,-523.5 -291.5,-1133.5 1284,-1133.5 ; 2173,-1133.5 2173,-523.5 ; 3440,-726.83 3440,-523.5 ; 4280,-726.83 4280,-523.5 ; 4902,-1140 4902,-937.17
  text "COMPONENTS MARKED 'DNP' SHOULD NOT BE POPULATED." at 1153.5,-318.5 h60
  text "ASSEMBLY VARIANT:" at 1153,-434 h60
  text ".VariantName" at 2189,-434 h60
  text "PCB VIEWED FROM TOP SIDE" at -228.5,-655.67 h60
  text "BOARD #:" at 2248,-655.67 h60
  text ".PRJ_Number" at 2793.5,-655.67 h60
  text "REV:" at 3638,-655.67 h60
  text ".PCB_Rev" at 3929.5,-655.67 h60
  text "SVN REV:" at 4476,-655.67 h60
  text ".VersionControl_RevNumber" at 4982,-655.67 h60
  text "TID #:" at 2248,-859 h60
  text ".TID" at 2793.5,-859 h60
  text "PLOT NAME =" at -228.5,-1064.34 h60
  text ".plot_File_Name" at 577,-1064.34 h60
  text "GENERATED    :" at 2250,-1064.34 h60
  text ".Print_Date" at 3119.5,-1064.34 h60
  text ".Print_Time" at 3848.5,-1064.34 h60
  text "TEXAS INSTRUMENTS" at 5113,-1064.34 h60
M6 Assembly Bottom:
  lines w10: -292.5,-727.33 6309.5,-727.33 ; -290.5,-930.67 6309.5,-930.67 ; 1115.5,-1140.5 1115.5,-937.67 ; 1737.5,-727.33 1737.5,-524 ; 2577.5,-727.33 2577.5,-524 ; 3844.5,-1134 3844.5,-524 ; 4733.5,-1134 6309,-1134 6309,-524 -292.5,-524 -292.5,-1134 2304.5,-1134 6309.5,-1134 6309.5,-524
  text "COMPONENTS MARKED 'DNP' SHOULD NOT BE POPULATED." at 6102,-318 h60
  text ".VariantName" at 5058,-434 h60
  text "ASSEMBLY VARIANT:" at 6097,-434 h60
  text ".VersionControl_RevNumber" at 1035.5,-656.17 h60
  text "SVN REV:" at 1541.5,-656.17 h60
  text ".PCB_Rev" at 2088,-656.17 h60
  text "REV:" at 2379.5,-656.17 h60
  text ".PRJ_Number" at 3224,-656.17 h60
  text "BOARD #:" at 3769.5,-656.17 h60
  text "PCB VIEWED FROM BOTTOM SIDE" at 6246,-656.17 h60
  text ".TID" at 3224,-859.5 h60
  text "TID #:" at 3769.5,-859.5 h60
  text "TEXAS INSTRUMENTS" at 904.5,-1064.84 h60
  text ".Print_Time" at 2169,-1064.84 h60
  text ".Print_Date" at 2898,-1064.84 h60
  text "GENERATED    :" at 3767.5,-1064.84 h60
  text ".plot_File_Name" at 5440.5,-1064.84 h60
  text "PLOT NAME =" at 6246,-1064.84 h60
M9 Title Sheet:
  drawing of 57 lines, arcs and shapes, not listed
  text "1" at 739.84,8036.5 h70
  text "2" at 3235.5,8036.5 h70
  text "3" at 5724.84,8036.5 h70
  text "4" at 8231.51,8036.5 h70
  text "5" at 10730.5,8036.5 h70
  text "6" at 13235.5,8036.5 h70
  text "A" at -416.5,6893.5 h70
  text "A" at 14383.5,6893.5 h70
  text "B" at -416.5,4513.5 h70
  text "B" at 14383.5,4513.5 h70
  text "C" at -416.5,2138.5 h70
  text "C" at 14383.5,2138.5 h70
  text "PROJECT TITLE:" at 11343.5,277.5 h45
  text ".PRJ_Title" at 11393.5,144.17 h70
  text "DESIGNED FOR:" at 11343.5,-23.5 h45
  text ".PRJ_Customer" at 11393.5,-163.5 h70
  text "D" at -416.5,-231.5 h70
  text "D" at 14383.5,-231.5 h70
  text "FILE NAME:" at 11343.5,-323.5 h45
  text ".PCB_File_Name_No_Path" at 11393.5,-443.5 h70
  text "Texas Instruments (TI) and/or its licensors do not warrant the accuracy or completeness of this specification" at 6374,-605.34 h45
  text "ENGINEER:" at 11343.5,-613.5 h45
  text "LAYOUT BY:" at 12848.5,-613.5 h45
  text "or any information contained therein. TI and/or its licensors do not warrant that this design will meet" at 6329.01,-718 h45
  text ".PRJ_Engineer" at 11393.5,-768.49 h70
  text ".PCB_Layout" at 12899,-768.49 h70
  text "the specifications, will be suitable for your application or fit for any particular purpose, or will operate in" at 6329.01,-830.67 h45
  text ".Layer_Name" at 577,-858.49 h60
  text "ALTIUM DESIGNER VERSION:" at 12848.5,-923.5 h45
  text "an implementation. TI and/or its licensors do not warrant that the design is production worthy. You should" at 6329.01,-943.33 h45
  text "completely validate and test your design implementation to confirm the system functionality for your application." at 6374,-1056 h45
  text ".print_Scale" at 11393.5,-1056.83 h70
  text ".Application_BuildNumber" at 12899,-1056.83 h70
  text "1" at 739.84,-1263.5 h70
  text "2" at 3235.5,-1263.5 h70
  text "3" at 5724.84,-1263.5 h70
  text "4" at 8231.51,-1263.5 h70
  text "5" at 10730.5,-1263.5 h70
  text "6" at 13235.5,-1263.5 h70
M10 Fab Notes:
  drawing of 173 lines, arcs and shapes, not listed
  text "DESIGN INFORMATION" at 12378.02,6201 h60
  text "MIN. TRACK WIDTH:" at 11733.46,6021 h60
  text "8" at 12829.7,6021 h60
  text "MIL" at 12984.46,6021 h60
  text "MIN. CLEARANCE:" at 11733.46,5889 h60
  text "0.2" at 12769.7,5889 h60
  text "mm" at 12984.46,5889 h60
  text "MIN. VIA PAD SIZE:" at 11733.46,5757 h60
  text "24" at 12799.71,5757 h60
  text "MIL" at 12984.46,5757 h60
  text "0.05mm (2MIL)" at 12428.46,5615.29 h60
  text "MINIMUM ANNULAR RING" at 11404.23,5611 h60
  text "EXTERNAL" at 13136.46,5611 h60
  text "PER" at 11604.23,5493 h60
  text "IPC-D-275 CLASS 2 LEVEL C" at 11824.23,5493 h60
  text "MIL, HOLES" at 13312.46,5380.71 h60
  text "+/-" at 12920,5380 h60
  text "+/-" at 13774,5380 h60
  text "REGISTRATION TOLERANCES:" at 11404.23,5375 h60
  text "METAL" at 12604,5375 h60
  text "5" at 13180.2,5375 h60
  text "3" at 14013.2,5375 h60
  text "MIL" at 14129.46,5375 h60
  text "+/-" at 13774,5262 h60
  text "HOLE SIZE TOLERANCE (UNLESS OTHERWISE SPECIFIED):" at 11404.23,5257 h60
  text "3" at 14013.2,5257 h60
  text "MIL" at 14129.46,5257 h60
  text "MATERIAL:" at 11329.46,5047.54 h60
  text "FR-4 High Tg" at 12315.9,4907.21 h60
  text "FR-408" at 11750.46,4898.64 h60
  text "OTHER" at 13238.46,4898.64 h60
  text "X" at 12161,4895 h60
  text "62 MIL (1.6mm) +/-10%" at 12070.56,4735.92 h60
  text "THICKNESS:" at 11404.23,4731.64 h60
  text "X" at 11942.4,4731.64 h60
  text "OTHER" at 13355.46,4731.64 h60
  text "TOLERANCE:" at 11404.23,4573.64 h60
  text "X" at 12243.53,4573.64 h60
  text "ANSI IPC-6012 TYPE 3 CLASS 2" at 12430.48,4573.64 h60
  text "OTHER +/-" at 12430.46,4417.64 h60
  text "BOW & TWIST:" at 11404.23,4260.64 h60
  text "X" at 12243.53,4260.64 h60
  text "ANSI IPC-6012 TYPE 3 CLASS 2" at 12430.48,4260.64 h60
  text "OTHER +/-" at 12430.46,4102.13 h60
  text "DRILLING:" at 11329.46,3963.64 h60
  text "REFERENCE:" at 11404.23,3846.64 h60
  text "X" at 12052.46,3846.64 h60
  text "AS SHOWN" at 12239.46,3846.64 h60
  text "X" at 12953.46,3846.64 h60
  text "NC_DRILL FILES" at 13090.46,3846.64 h60
  text "PTH COPPER THICKNESS:" at 11404.23,3688.64 h60
  text "X" at 12534.46,3688.64 h60
  text "20-30 um" at 12671.46,3688.64 h60
  text "OTHER" at 13388.46,3688.64 h60
  text "BOARD FINISH:" at 11329.46,3529.64 h60
  text "SILKSCREEN:" at 11484.68,3411.64 h60
  text "X" at 12433.46,3411.64 h60
  text "TOP" at 12559.46,3411.64 h60
  text "BOTTOM" at 13070.46,3411.64 h60
  text "SILKSCREEN COLOR:" at 11484.68,3244.64 h60
  text "X" at 12432.42,3244.64 h60
  text "WHITE" at 12559.46,3244.64 h60
  text "OTHER" at 13070.46,3244.64 h60
  text "X" at 12563.42,3085.44 h60
  text "GREEN" at 12690.46,3085.44 h60
  text "OTHER" at 13308.46,3085.44 h60
  text "SOLDER RESIST COLOR:" at 11484.68,3074.64 h60
  text "X" at 12563.42,2915.44 h60
  text "MATTE" at 12690.46,2915.44 h60
  text "SEMI-GLOSS" at 13308,2914.8 h60
  text "IMMERSION GOLD (ENIG)" at 12390.46,2726.92 h60
  text "ENEPIG" at 13728,2723.64 h60
  text "SURFACE FINISH:" at 11329.46,2722.64 h60
  text "X" at 12203.51,2722.64 h60
  text "IMM. TIN/SILVER OR EQUIV" at 11659,2565.64 h60
  text "OTHER" at 13090.46,2565.64 h60
  text "ARRAY/PANEL:" at 11329.46,2386.64 h60
  text "X" at 12189.18,2387.43 h60
  text "CUT AND TRIM PER M1 BOARD OUTLINE" at 12390.46,2382.35 h60
  text "N.C. ROUTE" at 12390.46,2230.64 h60
  text "V. SCORE" at 13256.46,2230.64 h60
  text "CERTIFICATION:" at 11329.46,2093.64 h60
  text "MATERIALS AND WORKMANSHIP FOR ALL PCBS" at 12054.46,2093.64 h60
  text "TO MEET OR EXCEED THE REQUIREMENTS OF:" at 12054.46,1995.64 h60
  text "X" at 11680.96,1859.13 h60
  text "ANSI IPC-A-600F CLASS ->" at 11819.96,1859.13 h60
  text "X" at 13459.02,1859.13 h60
  text "2" at 13577.96,1859.14 h60
  text "1" at 13262.96,1857.64 h60
  text "3" at 13931.96,1857.64 h60
  text "X" at 12495.02,1699.64 h60
  text "RoHS" at 12631.96,1699.64 h60
  text "OTHER" at 13276.36,1699.64 h60
  text "PER ORDER" at 13673.42,1699.64 h60
  text "ALL BOARDS MUST MEET OR EXCEED UL94-V0 REQUIREMENTS." at 11357,1534 h60
  text "PCB MUST BEAR THE UL94V-0 UL REGISTERED MATERIAL ID NUMBER" at 11357,1414 h60
  text "ADDITIONAL REQUIREMENTS:" at 11329.46,1240.64 h60
  text "MICROSECTION:" at 11404.23,1125.64 h60
  text "YES" at 12309.96,1125.64 h60
  text "REQUIRED" at 13171.46,969.49 h60
  text "BARE BOARD ELEC. TEST:" at 11404.23,966.64 h60
  text "NONE" at 12709.96,966.64 h60
  text "X" at 13044.46,966.64 h60
  text "PER ORDER" at 13763.46,966.64 h60
  text ".Layer_Name" at 577,-858.49 h60
M11 Gerber Information:
  lines w10: -292,-930.17 6308,-930.17 ; -292,-726.83 6310,-726.83 ; -292,-523.5 -292,-1133.5 3713,-1133.5 6310,-1133.5 6310,-523.5 -291.5,-523.5 -291.5,-1133.5 1284,-1133.5 ; 2173,-1133.5 2173,-523.5 ; 3440,-726.83 3440,-523.5 ; 4280,-726.83 4280,-523.5 ; 4902,-1140 4902,-937.17
  text "ALL ARTWORK VIEWED FROM TOP SIDE" at -228.5,-655.67 h60
  text "BOARD #:" at 2248,-655.67 h60
  text ".PRJ_Number" at 2793.5,-655.67 h60
  text "REV:" at 3638,-655.67 h60
  text ".PCB_Rev" at 3929.5,-655.67 h60
  text "SVN REV:" at 4476,-655.67 h60
  text ".VersionControl_RevNumber" at 4982,-655.67 h60
  text "LAYER NAME =" at -228.5,-858.49 h60
  text "TID #:" at 2248,-859 h60
  text ".TID" at 2793.5,-859 h60
  text "PLOT NAME =" at -228.5,-1064.34 h60
  text ".plot_File_Name" at 577,-1064.34 h60
  text "GENERATED    :" at 2250,-1064.34 h60
  text ".Print_Date" at 3119.5,-1064.34 h60
  text ".Print_Time" at 3848.5,-1064.34 h60
  text "TEXAS INSTRUMENTS" at 5113,-1064.34 h60
M12 Stackup:
  text ".Layer_Name" at 577,-858.49 h60
M13 Component Bodies Top:
  text ".Layer_Name" at 577,-858.49 h60
M14 Component Bodies Bottom:
  text ".Layer_Name" at 577,-858.49 h60
M15 Courtyards Top:
  text ".Layer_Name" at 577,-858.49 h60
M16 Courtyards Bottom:
  text ".Layer_Name" at 577,-858.49 h60
Drill Drawing:
  circle w10: c296.69,6274.37 r33.33
  lines w10: 263.35,6391.03 330.02,6391.03 330.02,6457.7 263.35,6457.7 263.35,6391.03 ; 263.35,6574.37 296.69,6541.03 330.02,6574.37 296.69,6607.7 263.35,6574.37 ; 263.35,6707.7 280.02,6707.7 280.02,6691.03 313.35,6691.03 313.35,6707.7 330.02,6707.7 330.02,6741.03 313.35,6741.03 313.35,6757.7 280.02,6757.7 280.02,6741.03 263.35,6741.03 263.35,6707.7
  lines w15: 203.56,6196.03 10724.65,6196.03 ; 203.56,6796.03 10724.65,6796.03 ; 754.44,6046.03 754.44,6946.03 ; 1344.28,6046.03 1344.28,6946.03 ; 2433.97,6046.03 2433.97,6946.03 ; 2939.84,6046.03 2939.84,6946.03 ; 3673.64,6046.03 3673.64,6946.03 ; 5173.19,6046.03 5173.19,6946.03 ; 5763.04,6046.03 5763.04,6946.03 ; 6508.84,6046.03 6508.84,6946.03 ; 7158.67,6046.03 7158.67,6946.03 ; 8012.43,6046.03 8012.43,6946.03 ; 9346.04,6046.03 9346.04,6946.03 ; 203.56,6046.03 10724.65,6046.03 10724.65,6946.03 203.56,6946.03 203.56,6046.03
  text "Symbol" at 293.56,6841.03 h72
  text "Count" at 799.44,6841.03 h72
  text "Hole Size" at 1389.28,6841.03 h72
  text "Plated" at 2478.97,6841.03 h72
  text "Hole Type" at 2984.84,6841.03 h72
  text "Drill Layer Pair" at 3718.64,6841.03 h72
  text "Via/Pad" at 5218.19,6841.03 h72
  text "Pad Shape" at 5808.04,6841.03 h72
  text "Template" at 6553.84,6841.03 h72
  text "Description" at 7203.67,6841.03 h72
  text "Hole Tolerance (+)" at 8057.43,6841.03 h72
  text "Hole Tolerance (-)" at 9391.04,6841.03 h72
  text "5" at 799.44,6691.03 h60
  text "7.87mil (0.200mm)" at 1389.28,6691.03 h60
  text "PTH" at 2478.97,6691.03 h60
  text "Round" at 2984.84,6691.03 h60
  text "Top Layer - Bottom Layer" at 3718.64,6691.03 h60
  text "Via" at 5218.19,6691.03 h60
  text "Rounded" at 5808.04,6691.03 h60
  text "v50h20m0" at 6553.84,6691.03 h60
  text "8" at 799.44,6541.03 h60
  text "47.24mil (1.200mm)" at 1389.28,6541.03 h60
  text "PTH" at 2478.97,6541.03 h60
  text "Round" at 2984.84,6541.03 h60
  text "Top Layer - Bottom Layer" at 3718.64,6541.03 h60
  text "Pad" at 5218.19,6541.03 h60
  text "(Mixed)" at 5808.04,6541.03 h60
  text "(Mixed)" at 6553.84,6541.03 h60
  text "9" at 799.44,6391.03 h60
  text "40.00mil (1.016mm)" at 1389.28,6391.03 h60
  text "PTH" at 2478.97,6391.03 h60
  text "Round" at 2984.84,6391.03 h60
  text "Top Layer - Bottom Layer" at 3718.64,6391.03 h60
  text "Pad" at 5218.19,6391.03 h60
  text "Rounded" at 5808.04,6391.03 h60
  text "c203h102" at 6553.84,6391.03 h60
  text "80" at 799.44,6241.03 h60
  text "12.00mil (0.305mm)" at 1389.28,6241.03 h60
  text "PTH" at 2478.97,6241.03 h60
  text "Round" at 2984.84,6241.03 h60
  text "Top Layer - Bottom Layer" at 3718.64,6241.03 h60
  text "Via" at 5218.19,6241.03 h60
  text "Rounded" at 5808.04,6241.03 h60
  text "(Mixed)" at 6553.84,6241.03 h60
  text "102 Total" at 799.44,6091.03 h60
  text ".Layer_Name" at 577,-858.49 h60
M17 Embedded Cavity:
  text ".Layer_Name" at 577,-858.49 h60
M18 Embedded Assembly:
  text ".Layer_Name" at 577,-858.49 h60
M19 Embedded Keepout:
  text ".Layer_Name" at 577,-858.49 h60

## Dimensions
0,-400 to 1000,-400 on M2 Board Dimensions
